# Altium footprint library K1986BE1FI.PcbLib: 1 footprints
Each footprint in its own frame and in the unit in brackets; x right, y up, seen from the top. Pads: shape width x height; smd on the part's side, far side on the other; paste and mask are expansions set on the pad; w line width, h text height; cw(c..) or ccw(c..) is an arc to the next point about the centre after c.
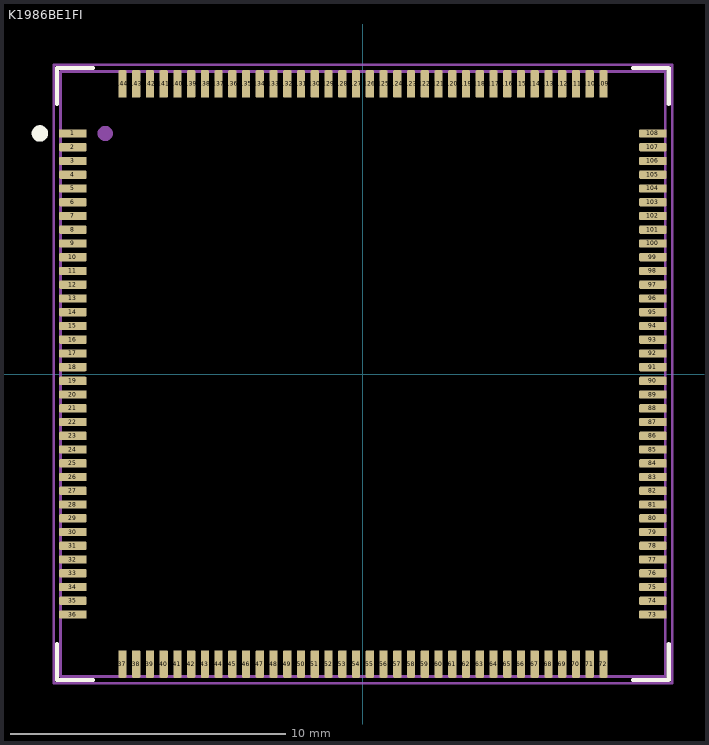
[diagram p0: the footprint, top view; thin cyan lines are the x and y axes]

## K1986BE1FI [mm] "QFN144 22x22x1,6(0,5)"
height 1.6
pads (144):
  rect 1x0.3 smd mask+0.05: 1(-10.55,8.75)
  rrect25% 1x0.3 smd mask+0.05: 2(-10.55,8.25) 3(-10.55,7.75) 4(-10.55,7.25) 5(-10.55,6.75) 6(-10.55,6.25) 7(-10.55,5.75) 8(-10.55,5.25) 9(-10.55,4.75) 10(-10.55,4.25) 11(-10.55,3.75) 12(-10.55,3.25) 13(-10.55,2.75) 14(-10.55,2.25) 15(-10.55,1.75) 16(-10.55,1.25) 17(-10.55,0.75) 18(-10.55,0.25) 19(-10.55,-0.25) 20(-10.55,-0.75) 21(-10.55,-1.25) 22(-10.55,-1.75) 23(-10.55,-2.25) 24(-10.55,-2.75) 25(-10.55,-3.25) 26(-10.55,-3.75) 27(-10.55,-4.25) 28(-10.55,-4.75) 29(-10.55,-5.25) 30(-10.55,-5.75) 31(-10.55,-6.25) 32(-10.55,-6.75) 33(-10.55,-7.25) 34(-10.55,-7.75) 35(-10.55,-8.25) 36(-10.55,-8.75) 73(10.55,-8.75) 74(10.55,-8.25) 75(10.55,-7.75) 76(10.55,-7.25) 77(10.55,-6.75) 78(10.55,-6.25) 79(10.55,-5.75) 80(10.55,-5.25) 81(10.55,-4.75) 82(10.55,-4.25) 83(10.55,-3.75) 84(10.55,-3.25) 85(10.55,-2.75) 86(10.55,-2.25) 87(10.55,-1.75) 88(10.55,-1.25) 89(10.55,-0.75) 90(10.55,-0.25) 91(10.55,0.25) 92(10.55,0.75) 93(10.55,1.25) 94(10.55,1.75) 95(10.55,2.25) 96(10.55,2.75) 97(10.55,3.25) 98(10.55,3.75) 99(10.55,4.25) 100(10.55,4.75) 101(10.55,5.25) 102(10.55,5.75) 103(10.55,6.25) 104(10.55,6.75) 105(10.55,7.25) 106(10.55,7.75) 107(10.55,8.25) 108(10.55,8.75)
  rrect25% 0.3x1 smd mask+0.05: 37(-8.75,-10.55) 38(-8.25,-10.55) 39(-7.75,-10.55) 40(-7.25,-10.55) 41(-6.75,-10.55) 42(-6.25,-10.55) 43(-5.75,-10.55) 44(-5.25,-10.55) 45(-4.75,-10.55) 46(-4.25,-10.55) 47(-3.75,-10.55) 48(-3.25,-10.55) 49(-2.75,-10.55) 50(-2.25,-10.55) 51(-1.75,-10.55) 52(-1.25,-10.55) 53(-0.75,-10.55) 54(-0.25,-10.55) 55(0.25,-10.55) 56(0.75,-10.55) 57(1.25,-10.55) 58(1.75,-10.55) 59(2.25,-10.55) 60(2.75,-10.55) 61(3.25,-10.55) 62(3.75,-10.55) 63(4.25,-10.55) 64(4.75,-10.55) 65(5.25,-10.55) 66(5.75,-10.55) 67(6.25,-10.55) 68(6.75,-10.55) 69(7.25,-10.55) 70(7.75,-10.55) 71(8.25,-10.55) 72(8.75,-10.55) 109(8.75,10.55) 110(8.25,10.55) 111(7.75,10.55) 112(7.25,10.55) 113(6.75,10.55) 114(6.25,10.55) 115(5.75,10.55) 116(5.25,10.55) 117(4.75,10.55) 118(4.25,10.55) 119(3.75,10.55) 120(3.25,10.55) 121(2.75,10.55) 122(2.25,10.55) 123(1.75,10.55) 124(1.25,10.55) 125(0.75,10.55) 126(0.25,10.55) 127(-0.25,10.55) 128(-0.75,10.55) 129(-1.25,10.55) 130(-1.75,10.55) 131(-2.25,10.55) 132(-2.75,10.55) 133(-3.25,10.55) 134(-3.75,10.55) 135(-4.25,10.55) 136(-4.75,10.55) 137(-5.25,10.55) 138(-5.75,10.55) 139(-6.25,10.55) 140(-6.75,10.55) 141(-7.25,10.55) 142(-7.75,10.55) 143(-8.25,10.55) 144(-8.75,10.55)
Top Overlay:
  circle w0.3: c-11.75,8.75 r0.15
  lines w0.15: -11.125,-9.825 -11.125,-11.125 -9.825,-11.125 ; -11.125,9.825 -11.125,11.125 -9.825,11.125 ; 9.825,-11.125 11.125,-11.125 11.125,-9.825 ; 9.825,11.125 11.125,11.125 11.125,9.825
Top Assembly:
  circle w0.3: c-9.375,8.75 r0.127
  lines w0.1: -11,-11 11,-11 11,11 -11,11 -11,-11
Top Courtyard:
  lines w0.1: -11.25,-11.25 11.25,-11.25 11.25,11.25 -11.25,11.25 -11.25,-11.25
3D body "Микросхема интегральная К1986ВЕ1FI_214.STEP": height 1.8, standoff 0, extent -11,-11 11,11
